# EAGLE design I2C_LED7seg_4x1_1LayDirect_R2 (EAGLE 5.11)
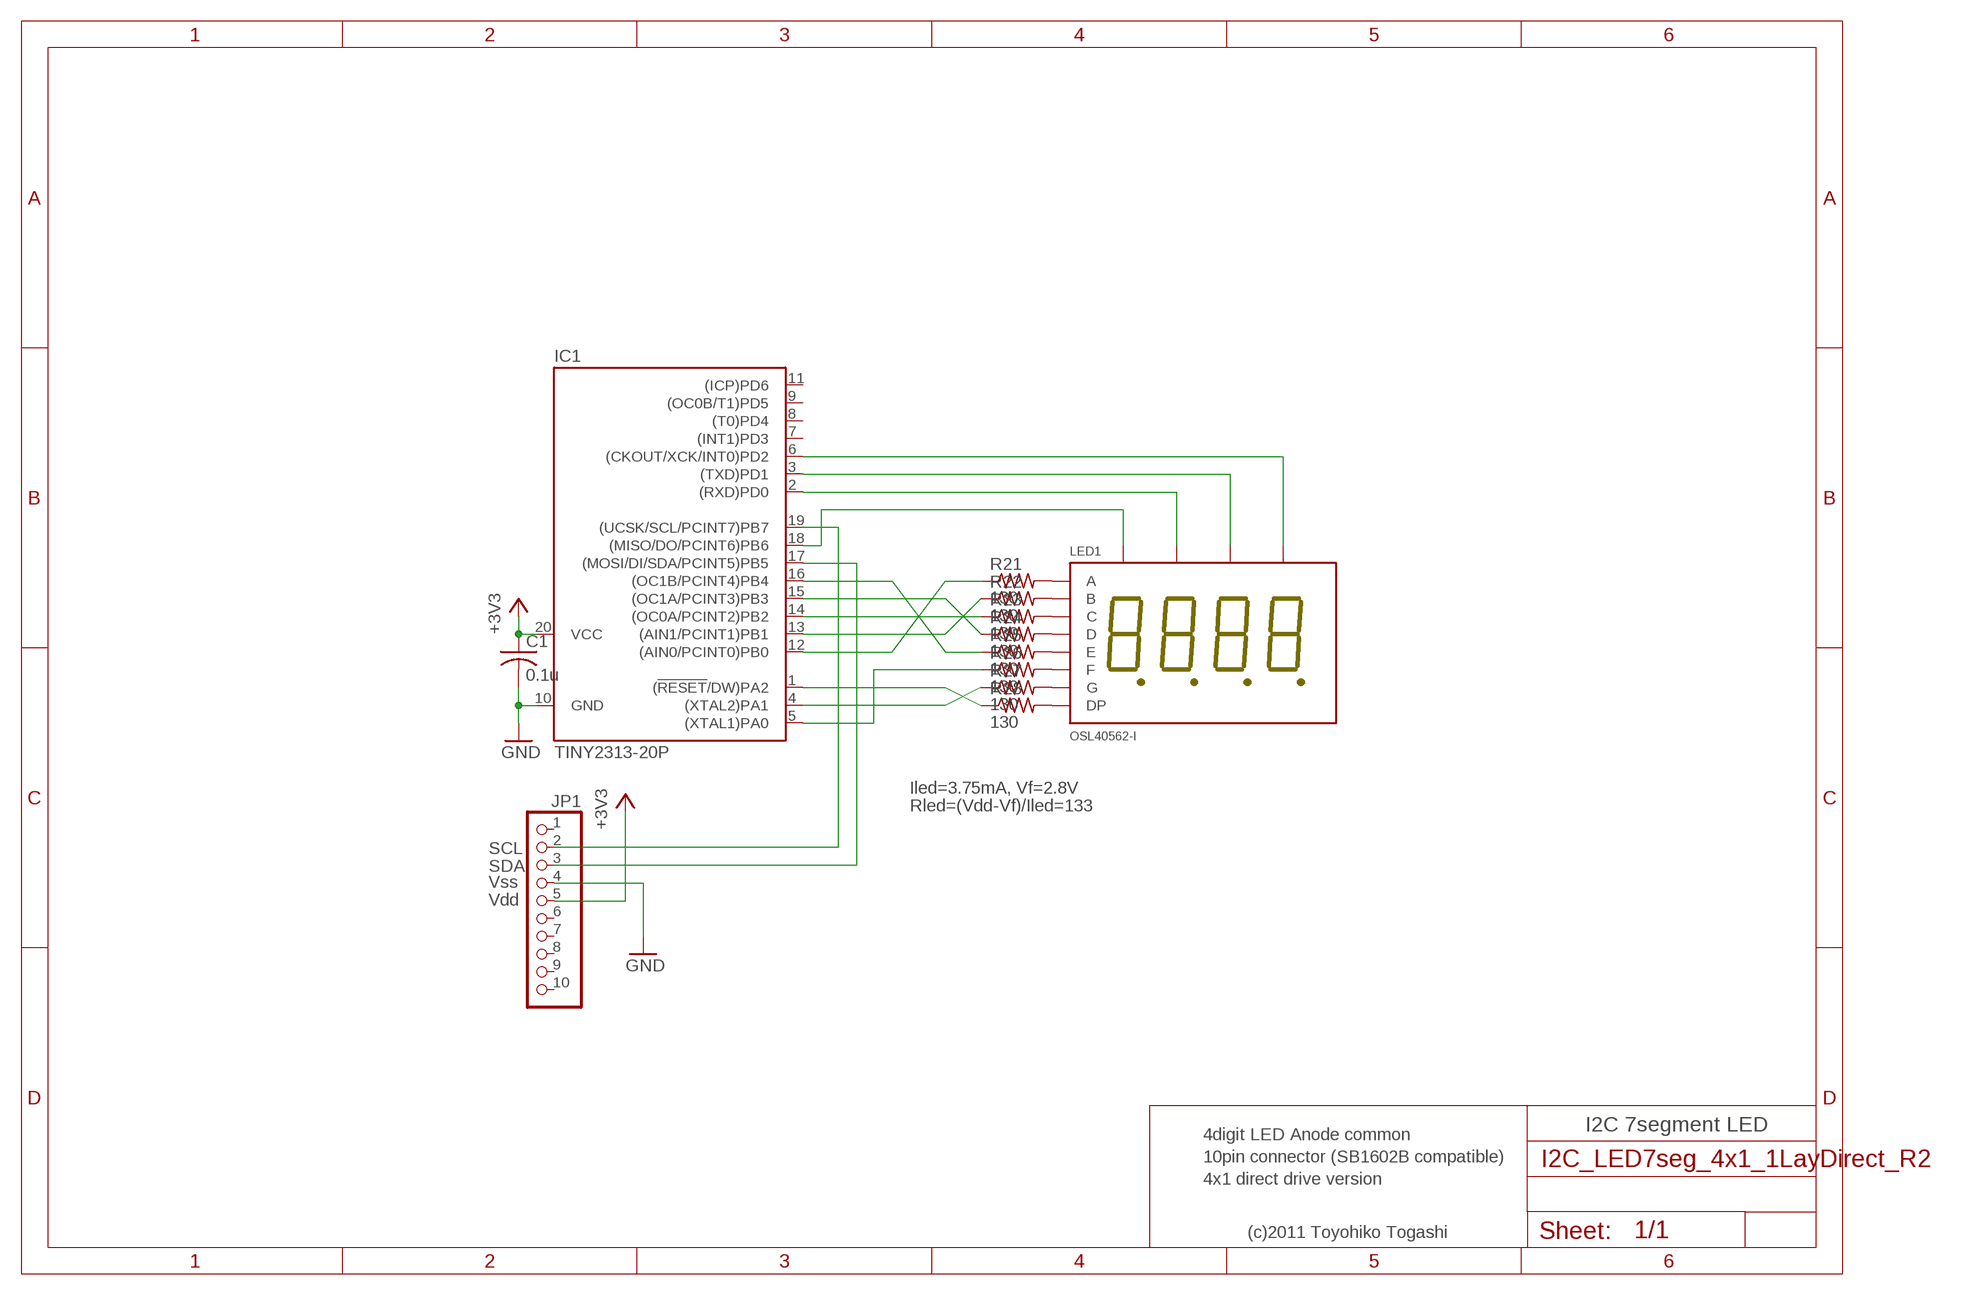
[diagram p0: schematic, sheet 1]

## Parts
C1  0.1u  C-US025-024X044  [C025-024X044]
IC1  TINY2313-20P  [DIL20]
JP1  PINHD-1X10  [1X10]
LED1  OSL40562-I  [OSL40562]
R21  130  R-US_0204/5  [0204/5]
R22  130  R-US_0204/5  [0204/5]
R23  130  R-US_0204/5  [0204/5]
R24  130  R-US_0204/5  [0204/5]
R25  130  R-US_0204/5  [0204/5]
R26  130  R-US_0204/7  [0204/7]
R27  130  R-US_0204/5  [0204/5]
R28  130  R-US_0204/5  [0204/5]

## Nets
+3V3: C1.1 IC1.20(VCC) JP1.5
GND: C1.2 IC1.10(GND) JP1.4
N$1: LED1.P$5(G) R27.2
N$2: LED1.P$3(DP) R28.2
N$3: IC1.19((UCSK/SCL/PCINT7)PB7) JP1.2
N$4: IC1.17((MOSI/DI/SDA/PCINT5)PB5) JP1.3
N$5: LED1.P$11(A) R21.2
N$6: LED1.P$7(B) R22.2
N$7: LED1.P$4(C) R23.2
N$8: LED1.P$2(D) R24.2
N$9: LED1.P$1(E) R25.2
N$10: LED1.P$10(F) R26.2
N$11: IC1.2((RXD)PD0) LED1.P$9(CA2)
N$12: IC1.18((MISO/DO/PCINT6)PB6) LED1.P$12(CA1)
N$13: IC1.3((TXD)PD1) LED1.P$8(CA3)
N$14: IC1.5((XTAL1)PA0) R26.1
N$15: IC1.4((XTAL2)PA1) R27.1
N$16: IC1.1((!RESET!/DW)PA2) R28.1
N$17: IC1.12((AIN0/PCINT0)PB0) R21.1
N$18: IC1.6((CKOUT/XCK/INT0)PD2) LED1.P$6(CA4)
N$19: IC1.13((AIN1/PCINT1)PB1) R22.1
N$20: IC1.14((OC0A/PCINT2)PB2) R23.1
N$21: IC1.15((OC1A/PCINT3)PB3) R24.1
N$22: IC1.16((OC1B/PCINT4)PB4) R25.1
Unconnected: IC1.7((INT1)PD3) IC1.8((T0)PD4) IC1.9((OC0B/T1)PD5) IC1.11((ICP)PD6) JP1.1 JP1.6 JP1.7 JP1.8 JP1.9 JP1.10

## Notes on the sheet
- Iled=3.75mA, Vf=2.8V
- Rled=(Vdd-Vf)/Iled=133
- SCL
- SDA
- Vss
- Vdd
- I2C 7segment LED
- 4digit LED Anode common
- 10pin connector (SB1602B compatible)
- 4x1 direct drive version
- (c)2011 Toyohiko Togashi

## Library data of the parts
C1 = rcl:C-US: CAPACITOR, American symbol
IC1 = TOG:TINY2313: 8-bit AVR Microcontroller with 2K Bytes Flash Source: http://www.atmel.com .. doc2543.pdf
JP1 = pinhead:PINHD-1X10: PIN HEADER
LED1 = TOG:OSL40562-I: OptSupply 7-Segmentx4 LED Common anode
R21-R28 = rcl:R-US_: RESISTOR, American symbol

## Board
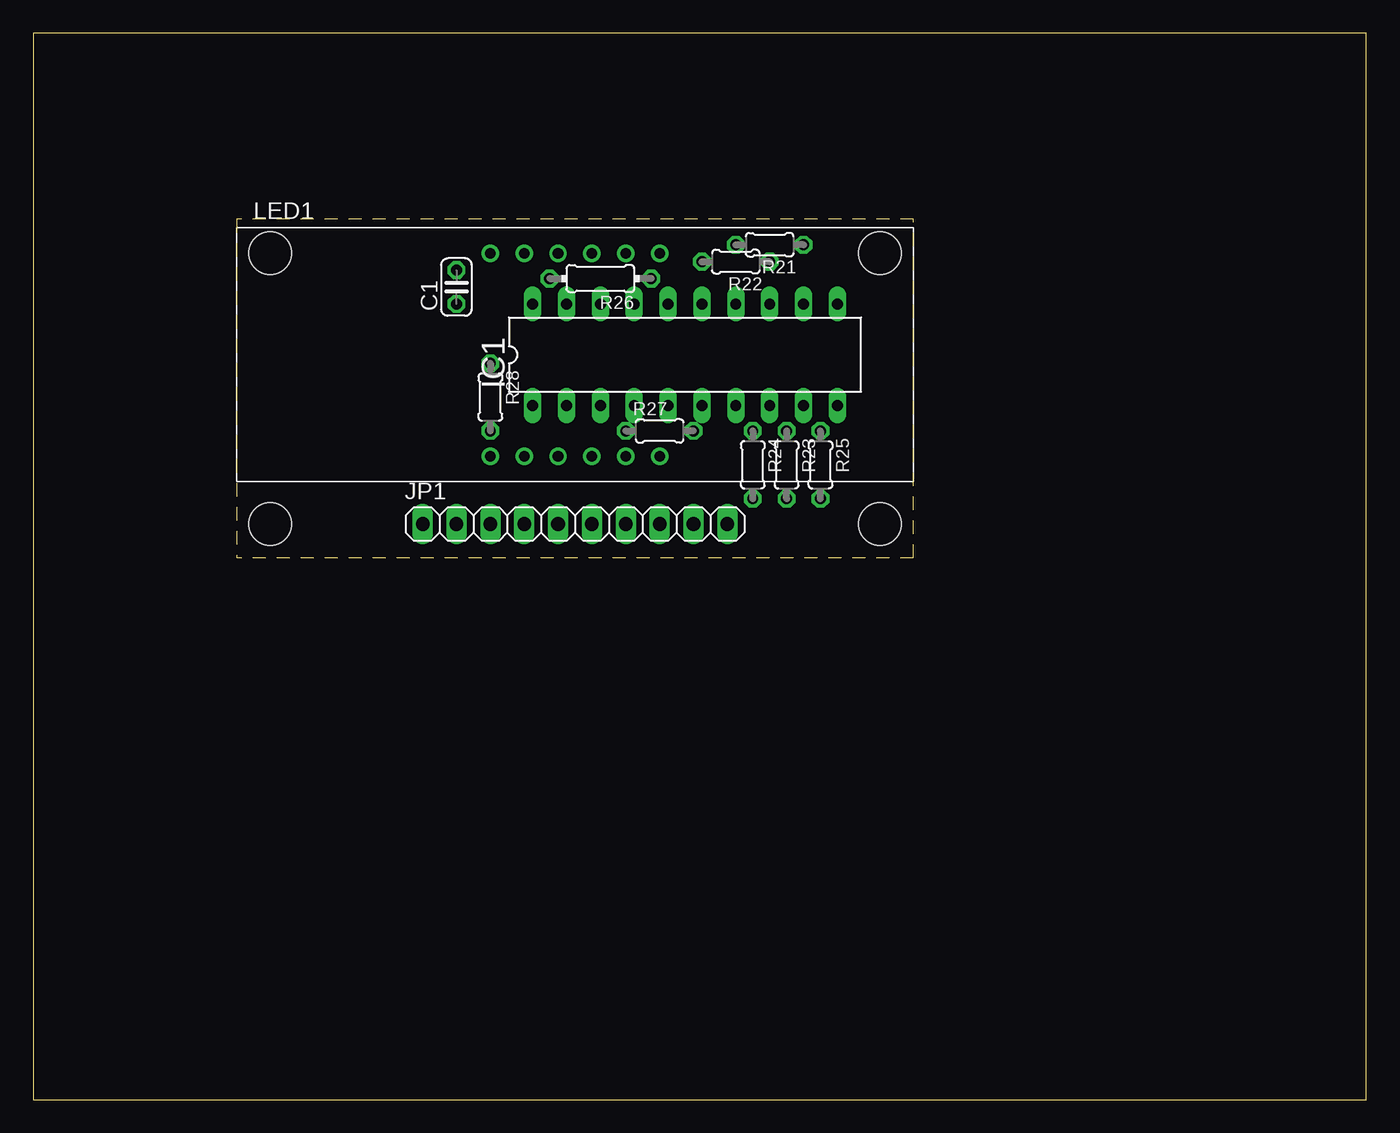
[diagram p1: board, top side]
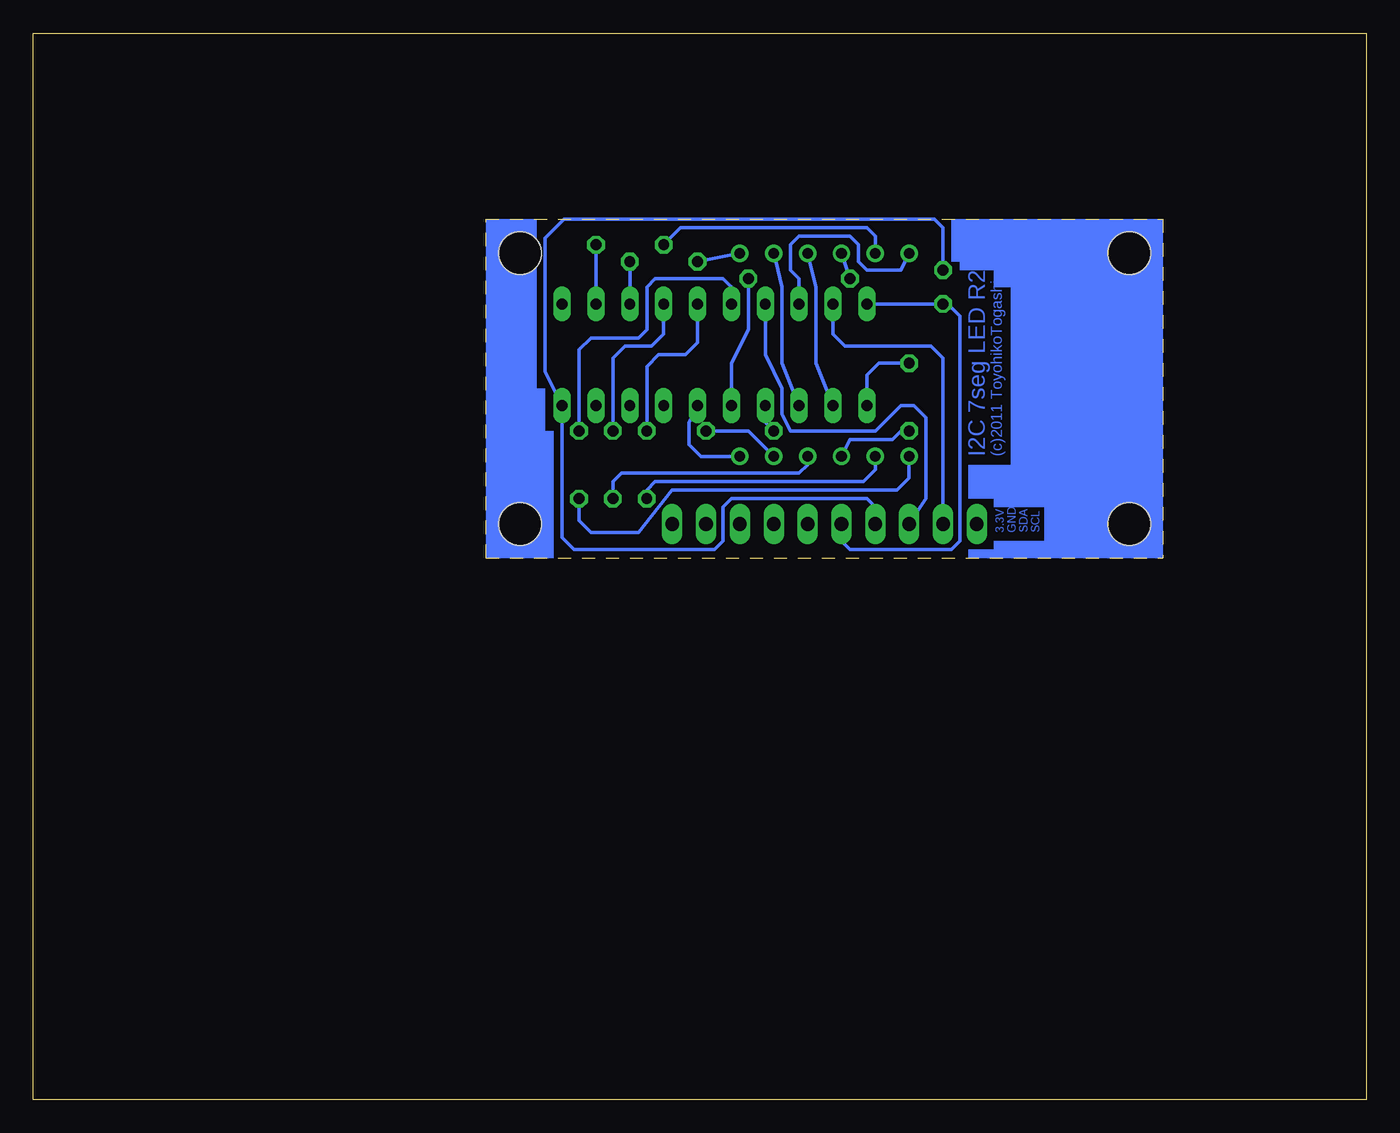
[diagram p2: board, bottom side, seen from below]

Size 100 x 80 mm. Coordinates in mm from the lower left corner, seen from the top.
Outline: 0,0 100,0 100,80 0,80 0,0
Outline: 15.24,66.04 15.24,40.64 66.04,40.64 66.04,66.04 15.24,66.04
Copper layers (1*16): Top 0.035mm / dielectric 1.5mm / Bottom 0.035mm
Design rules "default": minimum track width 10mil, minimum drill 24mil, track to track 8mil, track to pad 8mil, pad to pad 8mil, via to via 8mil, smd to smd 8mil, copper to edge 40mil, drill to drill 8mil, minimum pad ring 10mil, minimum via ring 8mil, stop-mask expansion 4mil, vias tented up to drill 0mil, thermal gap 10mil
Holes 3.2 mm at 63.5,43.18 17.78,43.18 17.78,63.5 63.5,63.5

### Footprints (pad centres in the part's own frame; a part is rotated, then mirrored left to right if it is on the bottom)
C025-024X044 = drill 0.813 octagon: 1 -1.27,0; 2 1.27,0
DIL20@1 = drill 0.813 long: 1 -11.43,-3.81; 2 -8.89,-3.81; 3 -6.35,-3.81; 4 -3.81,-3.81; 5 -1.27,-3.81; 6 1.27,-3.81; 7 3.81,-3.81; 8 6.35,-3.81; 9 8.89,-3.81; 10 11.43,-3.81; 11 11.43,3.81; 12 8.89,3.81; 13 6.35,3.81; 14 3.81,3.81; 15 1.27,3.81; 16 -1.27,3.81; 17 -3.81,3.81; 18 -6.35,3.81; 19 -8.89,3.81; 20 -11.43,3.81
1X10 = drill 1.016 long: 1 -11.43,0; 2 -8.89,0; 3 -6.35,0; 4 -3.81,0; 5 -1.27,0; 6 1.27,0; 7 3.81,0; 8 6.35,0; 9 8.89,0; 10 11.43,0
OSL40562 = drill 0.8 round: P$1 -6.35,-7.62; P$2 -3.81,-7.62; P$3 -1.27,-7.62; P$4 1.27,-7.62; P$5 3.81,-7.62; P$6 6.35,-7.62; P$7 6.35,7.62; P$8 3.81,7.62; P$9 1.27,7.62; P$10 -1.27,7.62; P$11 -3.81,7.62; P$12 -6.35,7.62
0204/5 = drill 0.813 octagon: 1 -2.54,0; 2 2.54,0
0204/7 = drill 0.813 octagon: 1 -3.81,0; 2 3.81,0

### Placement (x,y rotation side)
C1  31.75,60.96 90 top
IC1  TINY2313-20P  [DIL20@1]  48.9,55.88 0 top
JP1  40.64,43.18 0 top
LED1  40.64,55.88 0 top
R21  55.24,64.14 180 top
R22  52.7,62.87 180 top
R23  56.52,47.62 270 top
R24  53.98,47.62 270 top
R25  59.05,47.62 270 top
R26  42.55,61.59 180 top
R27  46.99,50.16 0 top
R28  34.29,52.7 270 top

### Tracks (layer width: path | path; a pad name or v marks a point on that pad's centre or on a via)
+3V3
  Bottom 0.254: IC1.20 C1.1 31.38,59.69 30.48,58.79 30.48,41.91 31.11,41.27 38.73,41.27 39.37,41.91 JP1.5
GND
  Bottom 0.254: JP1.4 36.83,44.45 37.47,45.09 47.62,45.09 48.26,44.45 48.26,41.91 48.9,41.27 59.43,41.27 60.33,42.17 IC1.10 61.59,54.61 61.59,64.62 60.17,66.04 32.38,66.04 31.75,65.41 C1.2
N$1
  Bottom 0.254: R27.2 46.35,50.16 LED1.P$5
N$2
  Bottom 0.254: LED1.P$3 38.73,49.53 35.56,49.53 34.92,50.16 R28.2
N$3
  Bottom 0.254: JP1.2 31.75,55.62 32.65,56.52 39.11,56.52 40.01,57.41 IC1.19
N$4
  Bottom 0.254: JP1.3 33.02,45.09 33.02,51.17 33.92,52.07 34.92,52.07 36.83,50.16 43.18,50.16 43.81,51.44 43.81,53.34 45.09,55.88 IC1.17
N$5
  Bottom 0.254: LED1.P$11 36.83,64.77 37.47,65.41 51.44,65.41 R21.2
N$6
  Bottom 0.254: R22.2 LED1.P$7
N$7
  Bottom 0.254: LED1.P$4 41.91,47.62 42.55,46.99 55.88,46.99 56.52,46.35 R23.2
N$8
  Bottom 0.254: LED1.P$2 36.83,47.25 37.73,46.35 53.34,46.35 53.98,45.72 R24.2
N$9
  Bottom 0.254: R25.2 59.05,43.44 58.16,42.55 54.61,42.55 52.07,45.72 35.19,45.72 34.29,46.62 LED1.P$1
N$10
  Bottom 0.254: LED1.P$10 R26.2
N$11
  Bottom 0.254: IC1.2 41.27,55.24 41.27,60.96 LED1.P$9
N$12
  Bottom 0.254: IC1.18 42.55,61.59 43.18,62.23 43.18,64.14 42.55,64.77 38.73,64.77 38.1,64.14 38.1,62.87 37.47,62.23 34.92,62.23 LED1.P$12
N$13
  Bottom 0.254: LED1.P$8 43.81,60.96 43.81,55.24 IC1.3
N$14
  Bottom 0.254: R26.1 46.35,57.78 47.62,55.24 IC1.5
N$15
  Bottom 0.254: IC1.4 45.09,50.8 R27.1
N$16
  Bottom 0.254: IC1.1 37.47,54.35 36.57,55.24 R28.1
N$17
  Bottom 0.254: R21.1 IC1.12
N$18
  Bottom 0.254: LED1.P$6 49.9,48.26 50.8,49.16 50.8,50.8 IC1.6
N$19
  Bottom 0.254: R22.1 IC1.13
N$20
  Bottom 0.254: R23.1 56.52,55.62 55.62,56.52 53.6,56.52 52.7,57.41 IC1.14
N$21
  Bottom 0.254: R24.1 53.98,54.98 53.08,55.88 51.06,55.88 50.16,56.78 IC1.15
N$22
  Bottom 0.254: R25.1 59.05,56.25 58.16,57.15 54.61,57.15 53.98,57.78 53.98,60.96 53.34,61.59 48.26,61.59 47.62,60.96 IC1.16
(copper drawn outside any net)
  shapes: Bottom area x20

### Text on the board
Bottom: (c)2011 ToyohikoTogashi | I2C 7seg LED R2 | SCL | SDA | GND | 3.3V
